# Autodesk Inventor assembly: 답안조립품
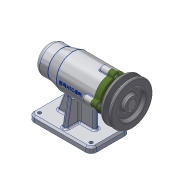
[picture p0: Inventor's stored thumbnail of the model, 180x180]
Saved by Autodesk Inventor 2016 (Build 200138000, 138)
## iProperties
Created: 2019-07
Part Number: 답안조립품
Material: 일반
Document SubType Name: Assembly
Designer: 605-12
Author: 605-12
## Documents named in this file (12)
- C:\Users\605-12\Desktop\490704V1074\답안조립품.iam
- C:\Users\605-12\Desktop\490704V1074\490704V1074.ipt
- C:\Users\605-12\Desktop\490704V1074\베어링 6004.ipt
- C:\Users\605-12\Desktop\490704V1074\축.ipt
- C:\Users\605-12\Desktop\490704V1074\베어링 51202.ipt
- C:\Users\605-12\Desktop\490704V1074\어댑터슬리브.ipt
- C:\Users\605-12\Desktop\490704V1074\볼트 M4.ipt
- C:\Users\605-12\Desktop\490704V1074\커버.ipt
- C:\Users\605-12\Desktop\490704V1074\오일 실.ipt
- C:\Users\605-12\Desktop\490704V1074\V벨트풀리.ipt
- C:\Users\605-12\Desktop\490704V1074\멈춤나사 M3.ipt
- C:\Users\605-12\Desktop\490704V1074\키 5 x 5 x 16.ipt
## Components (2 placed, 2 different names)
1. 490704V1074:1
2. V벨트풀리:1 — 각도:1
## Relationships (1: Angle 1)
- 각도:1 [Angle]: V벨트풀리:1
